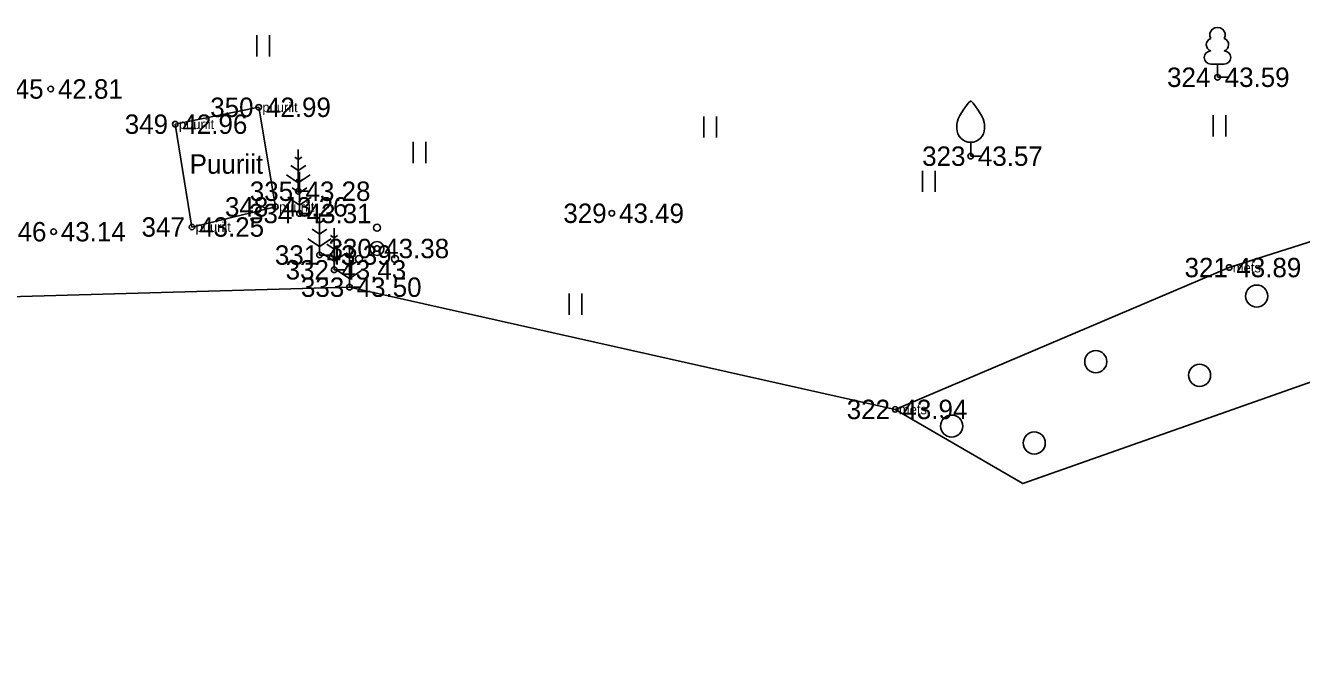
# Model space of a CAD drawing. Extents: x 505800 to 507326, y 6540058 to 6542128.
# Drawn here: x 506157.21 to 506203.25, y 6540216.5 to 6540239.39 of the extents above; entities that cross this region are included whole.
import ezdxf

# ---------------------------------------------------------------- set-up
doc = ezdxf.new("R2010")
doc.units = 0
for name, color, linetype in [('HALJASTUS', 7, 'Continuous'), ('KORGUS-EH2000', 7, 'Continuous'), ('MAAMUDEL', 7, 'Continuous'), ('MOOTKORG-EH2000', 7, 'Continuous'), ('MOOTMPUNKT', 7, 'Continuous'), ('MOOTNR', 7, 'Continuous'), ('MOOTPIIR', 7, 'Continuous'), ('PUU', 7, 'Continuous'), ('RAJATIS', 7, 'Continuous')]:
    doc.layers.add(name, color=color, linetype=linetype)

msp = doc.modelspace()

# ---------------------------------------------------------------- linework, layer by layer
at = {"layer": 'HALJASTUS'}
for p, q in [((506165.559, 6540239.04), (506165.559, 6540238.279)), ((506166.014, 6540239.04), (506166.014, 6540238.279)), ((506181.694, 6540236.116), (506181.694, 6540235.355)), ((506182.149, 6540236.116), (506182.149, 6540235.355)), ((506200.07, 6540236.156), (506200.07, 6540235.395)), ((506200.525, 6540236.156), (506200.525, 6540235.395)), ((506171.204, 6540235.194), (506171.204, 6540234.433)), ((506171.659, 6540235.194), (506171.659, 6540234.433)), ((506189.581, 6540234.153), (506189.581, 6540233.392)), ((506190.036, 6540234.153), (506190.036, 6540233.392)), ((506176.829, 6540229.726), (506176.829, 6540228.965)), ((506177.284, 6540229.726), (506177.284, 6540228.965))]:
    msp.add_line(p, q, dxfattribs=at)
msp.add_lwpolyline([(506188.596, 6540225.549), (506200.645, 6540230.665), (506209.16, 6540233.376), (506216.83, 6540236.009), (506219.751, 6540240.123), (506222.695, 6540240.784), (506230.801, 6540241.479), (506234.931, 6540239.99)], dxfattribs=at)
for centre in [(506201.639, 6540229.635), (506195.833, 6540227.271), (506199.577, 6540226.78), (506190.629, 6540224.947), (506193.611, 6540224.337)]:
    msp.add_circle(centre, 0.4, dxfattribs=at)
at = {"layer": 'KORGUS-EH2000'}
for centre in [(506200.224, 6540237.527), (506158.121, 6540237.105), (506165.628, 6540236.444), (506162.614, 6540235.835), (506191.318, 6540234.682), (506167.056, 6540233.417), (506166.229, 6540232.853), (506167.098, 6540232.613), (506178.37, 6540232.623), (506163.218, 6540232.127), (506158.225, 6540231.957), (506169.896, 6540231.351), (506167.821, 6540231.116), (506168.348, 6540230.583), (506200.645, 6540230.665), (506168.901, 6540229.957), (506188.596, 6540225.549)]:
    msp.add_circle(centre, 0.1, dxfattribs=at)
at = {"layer": 'MOOTMPUNKT'}
for centre in [(506200.224, 6540237.527), (506158.121, 6540237.105), (506165.628, 6540236.444), (506162.614, 6540235.835), (506191.318, 6540234.682), (506167.056, 6540233.417), (506166.229, 6540232.853), (506167.098, 6540232.613), (506178.37, 6540232.623), (506163.218, 6540232.127), (506158.225, 6540231.957), (506169.896, 6540231.351), (506167.821, 6540231.116), (506168.348, 6540230.583), (506200.645, 6540230.665), (506168.901, 6540229.957), (506188.596, 6540225.549)]:
    msp.add_circle(centre, 0.1, dxfattribs=at)
at = {"layer": 'MOOTPIIR'}
msp.add_lwpolyline([(506248.469, 6540250.071), (506234.931, 6540239.99), (506231.591, 6540236.406), (506193.196, 6540222.875), (506188.596, 6540225.549), (506168.901, 6540229.957), (506140.91, 6540229.168), (506108.07, 6540216.496), (506098.399, 6540223.506), (506079.917, 6540216.55)], dxfattribs=at)
at = {"layer": 'PUU'}
for p, q in [((506200.464, 6540238.002), (506199.984, 6540238.002)), ((506200.224, 6540237.527), (506200.224, 6540238.002)), ((506200.604, 6540237.527), (506200.224, 6540237.527)), ((506191.318, 6540234.682), (506191.318, 6540235.182)), ((506167.056, 6540234.567), (506166.932, 6540234.65)), ((506167.056, 6540234.917), (506167.056, 6540233.417)), ((506167.181, 6540234.65), (506167.056, 6540234.567)), ((506191.718, 6540234.682), (506191.318, 6540234.682)), ((506167.056, 6540234.167), (506166.79, 6540234.345)), ((506167.323, 6540234.345), (506167.056, 6540234.167)), ((506167.098, 6540234.113), (506167.098, 6540232.613)), ((506166.632, 6540234.007), (506167.056, 6540233.724)), ((506167.098, 6540233.763), (506166.974, 6540233.846)), ((506167.056, 6540233.724), (506167.481, 6540234.007)), ((506167.223, 6540233.846), (506167.098, 6540233.763)), ((506166.674, 6540233.202), (506167.098, 6540232.92)), ((506167.098, 6540233.363), (506166.831, 6540233.541)), ((506167.416, 6540233.417), (506167.056, 6540233.417)), ((506167.365, 6540233.541), (506167.098, 6540233.363)), ((506167.098, 6540232.92), (506167.522, 6540233.202)), ((506167.458, 6540232.613), (506167.098, 6540232.613)), ((506167.821, 6540232.266), (506167.696, 6540232.349)), ((506167.821, 6540232.616), (506167.821, 6540231.116)), ((506167.945, 6540232.349), (506167.821, 6540232.266)), ((506167.821, 6540231.866), (506167.554, 6540232.044)), ((506168.087, 6540232.044), (506167.821, 6540231.866)), ((506168.348, 6540231.733), (506168.223, 6540231.816)), ((506168.348, 6540232.083), (506168.348, 6540230.583)), ((506168.472, 6540231.816), (506168.348, 6540231.733)), ((506167.396, 6540231.706), (506167.821, 6540231.423)), ((506167.821, 6540231.423), (506168.245, 6540231.706)), ((506168.348, 6540231.333), (506168.081, 6540231.511)), ((506168.614, 6540231.511), (506168.348, 6540231.333)), ((506168.901, 6540231.457), (506168.901, 6540229.957)), ((506168.181, 6540231.116), (506167.821, 6540231.116)), ((506167.923, 6540231.172), (506168.348, 6540230.889)), ((506168.348, 6540230.889), (506168.772, 6540231.172)), ((506168.901, 6540230.707), (506168.635, 6540230.885)), ((506168.901, 6540231.107), (506168.777, 6540231.19)), ((506169.026, 6540231.19), (506168.901, 6540231.107)), ((506169.168, 6540230.885), (506168.901, 6540230.707)), ((506168.708, 6540230.583), (506168.348, 6540230.583)), ((506168.477, 6540230.547), (506168.901, 6540230.264)), ((506168.901, 6540230.264), (506169.325, 6540230.547)), ((506169.261, 6540229.957), (506168.901, 6540229.957))]:
    msp.add_line(p, q, dxfattribs=at)
for points in [[(506190.818, 6540235.682), (506190.818, 6540235.832), (506190.828, 6540235.897), (506190.863, 6540236.027), (506190.923, 6540236.147), (506191.068, 6540236.382), (506191.228, 6540236.587), (506191.318, 6540236.682)], [(506191.818, 6540235.682), (506191.818, 6540235.832), (506191.808, 6540235.897), (506191.773, 6540236.027), (506191.713, 6540236.147), (506191.568, 6540236.382), (506191.408, 6540236.587), (506191.318, 6540236.682)]]:
    msp.add_lwpolyline(points, dxfattribs=at)
for centre, radius in [((506169.896, 6540232.101), 0.125), ((506169.896, 6540231.351), 0.25), ((506169.246, 6540230.976), 0.125), ((506170.546, 6540230.976), 0.125)]:
    msp.add_circle(centre, radius, dxfattribs=at)
for centre, radius, start, end in [((506200.224, 6540239.047), 0.277, 332.5799, 207.4201), ((506200.054, 6540238.7), 0.233, 109.0217, 253.1415), ((506200.394, 6540238.7), 0.233, 286.8508, 70.9859), ((506199.987, 6540238.24), 0.238, 90.0016, 269.3953), ((506200.462, 6540238.24), 0.238, 270.6047, 89.9984), ((506191.318, 6540235.682), 0.5, 180, 0)]:
    msp.add_arc(centre, radius, start, end, dxfattribs=at)
at = {"layer": 'RAJATIS'}
msp.add_lwpolyline([(506162.614, 6540235.835), (506163.218, 6540232.127), (506166.229, 6540232.853), (506165.628, 6540236.444)], close=True, dxfattribs=at)

# ---------------------------------------------------------------- texts
at = {"layer": 'KORGUS-EH2000'}
for s, p in [(' 42.81', (506158.121, 6540236.755)), (' 42.99', (506165.628, 6540236.094)), (' 43.57', (506191.318, 6540234.332)), (' 43.49', (506178.37, 6540232.273)), (' 43.14', (506158.225, 6540231.607)), (' 43.38', (506169.896, 6540231.002)), (' 43.89', (506200.645, 6540230.315)), (' 43.94', (506188.596, 6540225.199))]:
    msp.add_text(s, height=0.7, dxfattribs=at).set_placement(p)
at = {"layer": 'MAAMUDEL'}
for s, p in [(' puuriit', (506165.628, 6540236.269)), (' puuriit', (506162.614, 6540235.66)), (' puuriit', (506166.229, 6540232.678)), (' puuriit', (506163.218, 6540231.952)), (' mets', (506200.645, 6540230.49)), (' mets', (506188.596, 6540225.374))]:
    msp.add_text(s, height=0.35, dxfattribs=at).set_placement(p)
at = {"layer": 'MOOTKORG-EH2000'}
for s, p in [(' 43.59', (506200.224, 6540237.177)), (' 42.81', (506158.121, 6540236.755)), (' 42.99', (506165.628, 6540236.094)), (' 42.96', (506162.614, 6540235.485)), (' 43.57', (506191.318, 6540234.332)), (' 43.28', (506167.056, 6540233.067)), (' 43.26', (506166.229, 6540232.503)), (' 43.31', (506167.098, 6540232.263)), (' 43.49', (506178.37, 6540232.273)), (' 43.14', (506158.225, 6540231.607)), (' 43.25', (506163.218, 6540231.777)), (' 43.39', (506167.821, 6540230.766)), (' 43.38', (506169.896, 6540231.002)), (' 43.43', (506168.348, 6540230.233)), (' 43.89', (506200.645, 6540230.315)), (' 43.50', (506168.901, 6540229.607)), (' 43.94', (506188.596, 6540225.199))]:
    msp.add_text(s, height=0.7, dxfattribs=at).set_placement(p)
at = {"layer": 'MOOTNR'}
for s, p in [('324 ', (506198.404, 6540237.177)), ('345 ', (506156.301, 6540236.755)), ('350 ', (506163.878, 6540236.094)), ('349 ', (506160.794, 6540235.485)), ('323 ', (506189.568, 6540234.332)), ('335 ', (506165.306, 6540233.067)), ('348 ', (506164.409, 6540232.503)), ('334 ', (506165.278, 6540232.263)), ('329 ', (506176.62, 6540232.273)), ('346 ', (506156.405, 6540231.607)), ('347 ', (506161.399, 6540231.777)), ('331 ', (506166.211, 6540230.766)), ('330 ', (506168.146, 6540231.002)), ('332 ', (506166.598, 6540230.233)), ('321 ', (506199.035, 6540230.315)), ('333 ', (506167.151, 6540229.607)), ('322 ', (506186.846, 6540225.199))]:
    msp.add_text(s, height=0.7, dxfattribs=at).set_placement(p)
at = {"layer": 'RAJATIS'}
msp.add_text('Puuriit', height=0.7, dxfattribs=at).set_placement((506163.134, 6540234.047))

doc.saveas('drawing.dxf')
